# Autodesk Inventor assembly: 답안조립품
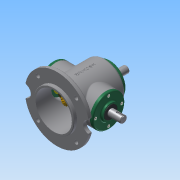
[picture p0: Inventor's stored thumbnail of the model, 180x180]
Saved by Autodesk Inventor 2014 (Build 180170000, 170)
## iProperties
Created: 2018-04
Part Number: 답안조립품
Document SubType Name: Assembly
Designer: net
Author: net
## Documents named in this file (16)
- C:\Users\net\Desktop\답안조립품.iam
- C:\Users\net\Desktop\부품2.ipt
- C:\Users\net\Desktop\메인 축.ipt
- 메인 축.ipt
- C:\Users\net\Desktop\서브 축.ipt
- 서브 축.ipt
- C:\Users\net\Desktop\커버.ipt
- C:\Users\net\Desktop\베어링 6203.ipt
- C:\Users\net\Desktop\오일 실.ipt
- 오일 실.ipt
- C:\Users\net\Desktop\키 5x5.ipt
- C:\Users\net\Desktop\메인 베벨기어.ipt
- C:\Users\net\Desktop\키 4x4.ipt
- C:\Users\net\Desktop\서브 베벨기어.ipt
- C:\Users\net\Desktop\볼트 M4.ipt
- 볼트 M4.ipt
